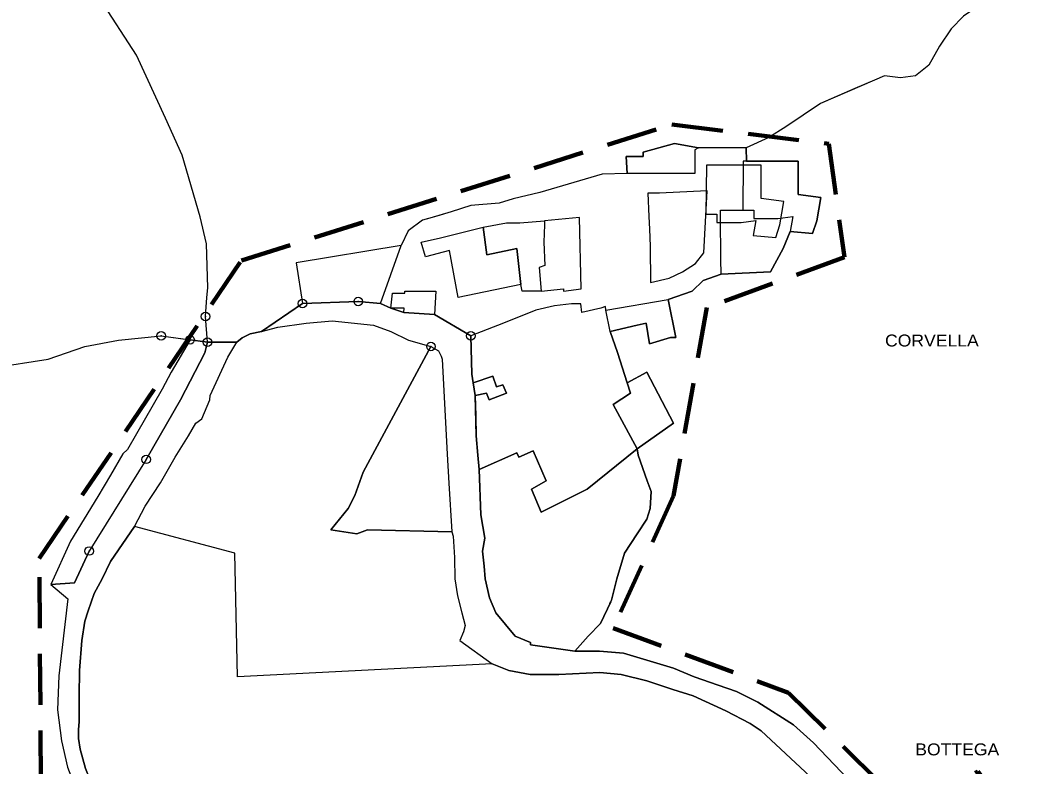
# Model space of a CAD drawing. Extents: x 654952 to 658955, y 890426 to 894481.
# Drawn here: x 657741.8 to 657975.8, y 893049.5 to 893224.6 of the extents above; entities that cross this region are included whole.
import ezdxf

# ---------------------------------------------------------------- set-up
doc = ezdxf.new("R2010")
doc.units = 0
doc.header["$LTSCALE"] = 4
doc.header["$PDMODE"] = 32
doc.header["$PDSIZE"] = 2
doc.linetypes.add('MEDIUM_DASHED', pattern=[4.5, 3, -1.5])
for name, color, linetype, lineweight in [('1', 7, 'Continuous', 25), ('18', 7, 'Continuous', 25), ('19', 7, 'Continuous', 25), ('31', 7, 'Continuous', 25), ('35', 7, 'Continuous', 25), ('5', 7, 'Continuous', 25), ('7', 7, 'MEDIUM_DASHED', 100), ('9', 7, 'Continuous', 25)]:
    doc.layers.add(name, color=color, linetype=linetype, lineweight=lineweight)
doc.layers.add('58', color=7, linetype='Continuous')

msp = doc.modelspace()

# ---------------------------------------------------------------- linework, layer by layer
at = {"layer": '1'}
for p, q in [((657889.5, 893171.44), (657889.63, 893162.94)), ((657798.37, 893151.44), (657808, 893158.03))]:
    msp.add_line(p, q, dxfattribs=at)
for points in [[(657912.02, 893194.55), (657900.89, 893194.55), (657895.27, 893195.55), (657887.89, 893193.55), (657887.9, 893192.54), (657883.89, 893192.55), (657884.14, 893188.55), (657878.25, 893188.39), (657863.64, 893184.05), (657857.39, 893182.55)], [(657906.16, 893164.91), (657917.75, 893165.44), (657920.75, 893170.94), (657922.37, 893174.94), (657927.63, 893174.44), (657928.63, 893177.44), (657929.54, 893182.92), (657924.25, 893183.62), (657924.25, 893191.44), (657912.13, 893191.44), (657912.02, 893194.55)], [(657889.63, 893162.94), (657894, 893163.94), (657897.13, 893165.44), (657900.13, 893167.44), (657902.13, 893169.94), (657902.87, 893184.44), (657891.75, 893183.94), (657889.03, 893183.94), (657889.25, 893178.44), (657889.37, 893175.44), (657889.5, 893171.44)], [(657857.39, 893182.55), (657854.14, 893181.55), (657847.52, 893181.05), (657842.89, 893179.55), (657839.52, 893178.55)], [(657839.52, 893178.55), (657836.14, 893177.55), (657832.77, 893175.05), (657831.16, 893171.66), (657806.52, 893167.55)], [(657806.52, 893167.55), (657808, 893158.03), (657821.09, 893158.47)], [(657858.25, 893122.94), (657858.75, 893121.94), (657862.13, 893123.44), (657865.13, 893116.44), (657861.75, 893114.44), (657863.99, 893109.05), (657874.75, 893114.44), (657886.5, 893123.94), (657880.89, 893134.28), (657884.9, 893136.95), (657881.89, 893146.55), (657880.13, 893151.44), (657886.5, 893152.94), (657888.63, 893153.44), (657889.39, 893148.55), (657894.27, 893150.05), (657895.52, 893150.05), (657893.75, 893158.94), (657899.37, 893160.94), (657902, 893163.44), (657906.16, 893164.91)], [(657821.09, 893158.47), (657826.32, 893157.98), (657828.75, 893156.94), (657831.75, 893155.94), (657839, 893155.44), (657847.5, 893150.44)], [(657881.89, 893146.55), (657880.12, 893151.44), (657879.13, 893156.44), (657879.08, 893157.28), (657878, 893156.94), (657873.5, 893155.94), (657873.25, 893157.94), (657871.13, 893157.94), (657867.13, 893157.44), (657862.75, 893156.44), (657855.13, 893153.44), (657847.5, 893150.44), (657847.75, 893141.44), (657848, 893139.44), (657852.63, 893140.94), (657853.5, 893138.44), (657855, 893138.94), (657855.87, 893136.94), (657851.75, 893135.44), (657851.13, 893136.94), (657848.5, 893136.44), (657848.63, 893131.69), (657848.75, 893126.94), (657849.13, 893122.44), (657849.46, 893119.03), (657858.25, 893122.94)], [(657847.5, 893150.44), (657847.75, 893141.44), (657848, 893139.44), (657848.5, 893136.44), (657848.75, 893126.94), (657849.13, 893122.44), (657849.46, 893119.03), (657858.25, 893122.94)], [(657884.9, 893136.95), (657884.15, 893139.41), (657881.89, 893146.55)], [(657858.25, 893122.94), (657858.75, 893121.94), (657862.13, 893123.44), (657865.13, 893116.44), (657861.75, 893114.44), (657863.99, 893109.05), (657874.75, 893114.44), (657886.5, 893123.94), (657880.89, 893134.28), (657884.9, 893136.95)]]:
    msp.add_lwpolyline(points, dxfattribs=at)
for points in [[(657887.89, 893193.55), (657895.27, 893195.55), (657900.9, 893194.54), (657900.02, 893194.05), (657900.02, 893188.55), (657884.14, 893188.55), (657883.9, 893192.54), (657887.89, 893192.55)], [(657911.37, 893191.44), (657911.25, 893179.94), (657913.87, 893179.94), (657913.87, 893177.94), (657919.5, 893177.94), (657923, 893178.44), (657922.37, 893174.94), (657927.63, 893174.44), (657928.63, 893177.44), (657929.54, 893182.92), (657924.25, 893183.62), (657924.25, 893191.44), (657912.13, 893191.44)], [(657902.71, 893190.49), (657902.59, 893178.99), (657905.21, 893178.99), (657905.21, 893176.99), (657910.84, 893176.99), (657914.34, 893177.49), (657913.71, 893173.99), (657918.97, 893173.49), (657919.97, 893176.49), (657920.88, 893181.97), (657915.59, 893182.67), (657915.59, 893190.49), (657903.47, 893190.49)], [(657911.25, 893179.94), (657913.87, 893179.94), (657913.87, 893177.94), (657919.5, 893177.94), (657923, 893178.44), (657922.37, 893174.94), (657920.75, 893170.94), (657917.75, 893165.44), (657906.16, 893164.91), (657906.13, 893168.44), (657906.02, 893178.44), (657906, 893179.94)], [(657851.25, 893169.44), (657850.37, 893175.94), (657855.87, 893176.94), (657859, 893176.94), (657864.78, 893177.45), (657864.75, 893176.44), (657864.63, 893172.44), (657864.87, 893166.94), (657863.5, 893166.44), (657864, 893160.94), (657859.5, 893160.94), (657859.25, 893162.44), (657858.25, 893170.94)], [(657864.75, 893176.44), (657864.63, 893172.44), (657864.87, 893166.94), (657863.5, 893166.44), (657864, 893160.94), (657869.25, 893161.44), (657869.25, 893160.94), (657873.37, 893161.44), (657872.98, 893178.18), (657864.78, 893177.45)], [(657842.5, 893170.44), (657836.87, 893168.94), (657835.87, 893172.44), (657840.37, 893173.44), (657845.37, 893174.69), (657850.37, 893175.94), (657851.25, 893169.44), (657858.25, 893170.94), (657859.25, 893162.44), (657844.5, 893159.44)], [(657808, 893158.03), (657821.09, 893158.47), (657826.32, 893157.98), (657831.14, 893171.64), (657806.5, 893167.53)], [(657829.13, 893160.44), (657832, 893160.44), (657832, 893160.94), (657839.25, 893160.94), (657839, 893155.44), (657831.75, 893155.94), (657831.87, 893156.94), (657828.75, 893156.94)], [(657879.13, 893156.44), (657893.75, 893158.94), (657895.52, 893150.05), (657894.27, 893150.05), (657889.39, 893148.55), (657888.63, 893153.44), (657886.5, 893152.94), (657880.12, 893151.44)], [(657852.63, 893140.94), (657848, 893139.44), (657848.5, 893136.44), (657851.13, 893136.94), (657851.75, 893135.44), (657855.87, 893136.94), (657855, 893138.94), (657853.5, 893138.44)]]:
    msp.add_lwpolyline(points, close=True, dxfattribs=at)
for p in [(657808, 893158.03), (657821.09, 893158.47), (657847.5, 893150.44)]:
    msp.add_point(p, dxfattribs=at)
at = {"layer": '18'}
for p, q in [((657781.65, 893149.49), (657777.25, 893141.94)), ((657777.25, 893141.94), (657775.13, 893137.94))]:
    msp.add_line(p, q, dxfattribs=at)
for points in [[(657771.37, 893121.44), (657779.37, 893135.44), (657785.13, 893146.44), (657785.75, 893148.94), (657781.65, 893149.49)], [(657843, 893104.44), (657823.25, 893104.94), (657820.75, 893103.94), (657814.63, 893104.94), (657818.75, 893109.94), (657820.25, 893112.94), (657822.25, 893118.44), (657838.13, 893147.94), (657839.88, 893146.94), (657840.19, 893146.31), (657840.5, 893145.69), (657840.75, 893144.94)], [(657840.75, 893144.94), (657841.94, 893122.69), (657842.34, 893115.86), (657843, 893104.44)], [(657775.13, 893137.94), (657767.01, 893123.73), (657765.88, 893122.73), (657763.01, 893117.73), (657760.01, 893112.73), (657753.63, 893102.23), (657749.02, 893092.12), (657754.58, 893092.44), (657758, 893099.94)]]:
    msp.add_lwpolyline(points, dxfattribs=at)
for p in [(657781.65, 893149.49), (657771.37, 893121.44), (657758, 893099.94)]:
    msp.add_point(p, dxfattribs=at)
at = {"layer": '19'}
for points in [[(657768.62, 893105.66), (657763, 893097.44), (657761, 893093.44), (657759.13, 893089.94), (657757.75, 893085.94), (657757, 893083.44), (657756.25, 893078.94), (657755.75, 893071.94), (657755.63, 893065.94), (657755.63, 893059.94), (657755.5, 893057.94), (657755.5, 893055.94), (657755.88, 893053.44), (657756.5, 893051.19), (657757.13, 893048.94), (657758.13, 893046.44), (657759.48, 893042.94), (657927.42, 893042.94), (657927.02, 893047.01), (657915.59, 893057.77)], [(657915.59, 893057.77), (657913, 893059.44), (657907.25, 893062.44), (657899.63, 893065.94), (657894.87, 893067.44), (657888.75, 893069.44), (657882.75, 893070.94), (657877.75, 893071.44), (657868.13, 893070.94), (657861.37, 893070.94), (657856.37, 893071.94), (657852.5, 893073.44), (657792.75, 893070.44), (657792.13, 893099.44), (657768.62, 893105.66)]]:
    msp.add_lwpolyline(points, dxfattribs=at)
at = {"layer": '31'}
for points in [[(657993.63, 893244.44), (657991.13, 893240.44), (657986.37, 893235.94), (657980.75, 893232.44), (657975.13, 893230.44), (657969.25, 893228.44), (657966, 893227.44), (657963, 893225.44), (657960.13, 893222.44), (657957.38, 893218.44), (657954.87, 893213.94), (657951.75, 893211.44), (657948.25, 893210.94), (657945.7, 893211.28)], [(657945.7, 893211.28), (657944.5, 893211.44), (657942.13, 893210.44), (657937.5, 893208.44), (657929.5, 893204.94), (657921.37, 893199.44), (657917.37, 893196.94), (657912.02, 893194.55), (657912.13, 893191.44), (657924.25, 893191.44), (657924.25, 893183.62), (657929.54, 893182.92), (657928.63, 893177.44), (657927.63, 893174.44), (657922.37, 893174.94), (657920.75, 893170.94), (657917.75, 893165.44), (657906.16, 893164.91), (657902, 893163.44), (657899.37, 893160.94), (657893.75, 893158.94), (657895.52, 893150.05), (657894.27, 893150.05), (657889.39, 893148.55), (657888.63, 893153.44), (657886.5, 893152.94), (657880.13, 893151.44)], [(657880.13, 893151.44), (657881.89, 893146.55), (657884.15, 893139.41), (657888.75, 893141.94), (657895, 893129.94), (657886.5, 893123.94), (657886.75, 893122.44), (657888.87, 893116.44)], [(657665.82, 893118.07), (657670.25, 893120.44), (657680.87, 893126.44), (657687.75, 893128.94), (657694.75, 893130.94), (657702.5, 893134.44), (657710.63, 893136.94), (657723.13, 893140.44), (657735.25, 893142.94), (657748.37, 893144.94), (657757, 893147.94), (657764.87, 893149.44), (657774.87, 893150.44), (657781.65, 893149.49), (657777.25, 893141.94), (657775.13, 893137.94)], [(657775.13, 893137.94), (657767.01, 893123.73), (657765.88, 893122.73), (657763.01, 893117.73), (657760.01, 893112.73), (657753.63, 893102.23), (657749.02, 893092.12)], [(657888.87, 893116.44), (657889.75, 893113.94), (657889.5, 893109.94), (657888.75, 893107.44), (657886.5, 893103.94), (657883.5, 893099.44), (657881.75, 893093.44), (657880.5, 893088.44), (657880.1, 893087.6), (657880.3, 893088.02), (657877.87, 893082.94), (657875, 893079.94), (657871.87, 893076.44), (657877.63, 893076.44), (657883.25, 893075.94), (657895, 893072.44), (657899.87, 893070.44), (657905.5, 893068.44), (657909.75, 893066.94), (657914.75, 893064.44), (657923.17, 893059.18), (657927.87, 893054.94), (657935.94, 893046.44)], [(657749.02, 893092.12), (657753.01, 893088.7), (657750.86, 893070.62), (657750.6, 893062.66), (657751.53, 893055.36), (657752.89, 893049.18), (657758.65, 893034.52), (657762.55, 893024.6), (657763.91, 893018.16), (657764.24, 893010.53), (657763.29, 893003.28), (657761.19, 892995.37), (657758, 892987.59), (657738.18, 893003.15)]]:
    msp.add_lwpolyline(points, dxfattribs=at)
at = {"layer": '35'}
for p, q in [((657808, 893158.03), (657798.37, 893151.44)), ((657774.87, 893150.44), (657785.75, 893148.94))]:
    msp.add_line(p, q, dxfattribs=at)
for points in [[(657785.75, 893148.94), (657785.25, 893154.99), (657785.55, 893159.43), (657785.79, 893161.68), (657785.49, 893172.03), (657783.98, 893178.37), (657779.79, 893192.83), (657775.91, 893201.54), (657769.07, 893216.31), (657760.53, 893229.52)], [(657785.25, 893154.99), (657785.55, 893159.43), (657785.79, 893161.68), (657785.49, 893172.03), (657783.98, 893178.37), (657779.79, 893192.83), (657775.91, 893201.54), (657769.07, 893216.31), (657760.53, 893229.52)], [(657963, 893225.44), (657960.13, 893222.44), (657957.38, 893218.44), (657954.87, 893213.94), (657951.75, 893211.44), (657948.25, 893210.94), (657945.7, 893211.28), (657944.5, 893211.44), (657942.13, 893210.44), (657929.5, 893204.94), (657921.37, 893199.44), (657917.37, 893196.94), (657912.02, 893194.55), (657900.9, 893194.54), (657895.28, 893195.54), (657887.89, 893193.55), (657887.9, 893192.54), (657883.9, 893192.54), (657884.14, 893188.55), (657878.25, 893188.39), (657863.64, 893184.05), (657857.39, 893182.55), (657854.14, 893181.54), (657847.52, 893181.04), (657842.89, 893179.55), (657837.84, 893178.04), (657836.14, 893177.54), (657832.78, 893175.04), (657831.16, 893171.66), (657806.52, 893167.54), (657808, 893158.03)], [(657798.37, 893151.44), (657795.75, 893150.94), (657793.87, 893149.94), (657792.63, 893148.94), (657785.75, 893148.94), (657785.25, 893154.99)], [(657676.59, 893105.59), (657670.27, 893111.6), (657665.82, 893118.07), (657680.87, 893126.44), (657687.75, 893128.94), (657694.75, 893130.94), (657702.5, 893134.44), (657723.13, 893140.44), (657735.25, 893142.94), (657748.37, 893144.94), (657757, 893147.94), (657764.87, 893149.44), (657774.87, 893150.44)]]:
    msp.add_lwpolyline(points, dxfattribs=at)
for p in [(657785.25, 893154.99), (657774.87, 893150.44), (657785.75, 893148.94)]:
    msp.add_point(p, dxfattribs=at)
at = {"layer": '5'}
for points in [[(657850.59, 893096.42), (657850.25, 893099.94), (657850.75, 893102.94), (657849.87, 893108.44), (657849.46, 893119.03), (657849.13, 893122.44), (657848.75, 893126.94), (657848.5, 893136.44), (657848, 893139.44), (657847.75, 893141.44), (657847.5, 893150.44), (657839, 893155.44), (657831.75, 893155.94), (657828.75, 893156.94), (657826.32, 893157.98), (657821.09, 893158.47), (657808, 893158.03), (657798.37, 893151.44)], [(657808.84, 893153.4), (657815, 893153.94), (657824.63, 893152.94), (657828.75, 893151.44), (657832.88, 893149.44), (657838.13, 893147.94), (657839.88, 893146.94), (657840.19, 893146.31), (657840.5, 893145.69), (657840.75, 893144.94)], [(657798.37, 893151.44), (657802.25, 893152.44), (657808.84, 893153.4)], [(657840.75, 893144.94), (657841.94, 893122.69), (657842.34, 893115.86), (657843, 893104.44)], [(657843, 893104.44), (657843.37, 893103.44), (657843.63, 893098.44), (657843.75, 893093.44), (657844.37, 893089.44), (657845.37, 893085.44), (657846.13, 893082.44), (657845.75, 893080.94), (657844.87, 893078.94), (657852.5, 893073.44), (657856.37, 893071.94)], [(657935.94, 893046.44), (657927.87, 893054.94), (657923.17, 893059.18), (657914.75, 893064.44), (657909.75, 893066.94), (657905.5, 893068.44), (657899.87, 893070.44), (657895, 893072.44), (657883.25, 893075.94), (657877.63, 893076.44), (657871.87, 893076.44), (657861.5, 893077.94), (657861.5, 893078.44), (657857.87, 893079.94), (657853.37, 893085.44), (657851.87, 893088.94), (657850.87, 893093.44), (657850.59, 893096.42)], [(657856.37, 893071.94), (657861.37, 893070.94), (657868.13, 893070.94), (657877.75, 893071.44), (657882.75, 893070.94), (657888.75, 893069.44), (657894.87, 893067.44), (657899.63, 893065.94), (657907.25, 893062.44), (657913, 893059.44), (657915.59, 893057.77), (657927.02, 893047.01)]]:
    msp.add_lwpolyline(points, dxfattribs=at)
at = {"layer": '7'}
msp.add_lwpolyline([(657691.52, 892856.93), (657700.1, 892905.18), (657716.04, 892939.12), (657738.11, 892964.47), (657720.54, 892980.83), (657736.88, 893006.17), (657758.54, 892994.31), (657762.63, 893015.17), (657746.69, 893045.84), (657746.28, 893098.18), (657793.69, 893168.1), (657894.63, 893200), (657931.41, 893195.5), (657935.09, 893168.92), (657902.81, 893157.06), (657895.04, 893112.9), (657880.84, 893081.86), (657922.01, 893066.69), (657950.13, 893038.88), (657966.34, 893048.2), (657980.93, 893028.74)], dxfattribs=at)
at = {"layer": '9'}
for p, q in [((657785.75, 893148.94), (657792.63, 893148.94)), ((657771.37, 893121.44), (657758, 893099.94))]:
    msp.add_line(p, q, dxfattribs=at)
for points in [[(657808.84, 893153.4), (657815, 893153.94), (657824.63, 893152.94), (657828.75, 893151.44), (657832.88, 893149.44), (657838.13, 893147.94)], [(657786.25, 893135.44), (657786.37, 893136.44), (657790.5, 893145.44), (657792.63, 893148.94), (657793.87, 893149.94), (657795.75, 893150.94), (657798.37, 893151.44), (657802.25, 893152.44), (657808.84, 893153.4)], [(657786.25, 893135.44), (657786.37, 893136.44), (657790.5, 893145.44), (657792.63, 893148.94), (657785.75, 893148.94), (657785.13, 893146.44), (657779.37, 893135.44), (657771.37, 893121.44)], [(657838.13, 893147.94), (657822.25, 893118.44), (657820.25, 893112.94), (657818.75, 893109.94), (657814.63, 893104.94), (657820.75, 893103.94), (657823.25, 893104.94), (657843, 893104.44)], [(657771.13, 893110.44), (657774.75, 893115.94), (657778.13, 893121.94), (657781.25, 893126.94), (657783, 893129.94), (657784.37, 893130.94), (657786.25, 893135.44)], [(657771.13, 893110.44), (657774.75, 893115.94), (657778.13, 893121.94), (657781.25, 893126.94), (657783, 893129.94), (657784.37, 893130.94), (657786.25, 893135.44)], [(657863.99, 893109.05), (657861.75, 893114.44), (657865.13, 893116.44), (657862.13, 893123.44), (657858.75, 893121.94), (657858.25, 893122.94)], [(657880.1, 893087.6), (657880.5, 893088.44), (657881.75, 893093.44), (657883.5, 893099.44), (657886.5, 893103.94), (657888.75, 893107.44), (657889.5, 893109.94), (657889.75, 893113.94), (657888.87, 893116.44), (657886.75, 893122.44), (657886.5, 893123.94), (657874.75, 893114.44), (657863.99, 893109.05)], [(657858.25, 893122.94), (657849.46, 893119.03), (657849.87, 893108.44), (657850.75, 893102.94)], [(657755.63, 893059.94), (657755.63, 893065.94), (657755.75, 893071.94), (657756.25, 893078.94), (657757, 893083.44), (657757.75, 893085.94), (657759.13, 893089.94), (657761, 893093.44), (657763, 893097.44), (657768.62, 893105.66), (657771.13, 893110.44)], [(657852.5, 893073.44), (657792.75, 893070.44), (657792.13, 893099.44), (657768.62, 893105.66), (657771.13, 893110.44)], [(657843, 893104.44), (657843.37, 893103.44), (657843.63, 893098.44), (657843.75, 893093.44), (657844.37, 893089.44), (657845.37, 893085.44), (657846.13, 893082.44), (657845.75, 893080.94), (657844.87, 893078.94), (657852.5, 893073.44)], [(657850.75, 893102.94), (657850.25, 893099.94), (657850.59, 893096.42), (657850.87, 893093.44), (657851.87, 893088.94), (657853.37, 893085.44), (657857.87, 893079.94), (657861.5, 893078.44), (657861.5, 893077.94), (657871.87, 893076.44), (657875, 893079.94), (657877.87, 893082.94), (657880.3, 893088.02), (657880.1, 893087.6)], [(657758, 893099.94), (657754.58, 893092.44), (657749.02, 893092.12)], [(657749.02, 893092.12), (657753.01, 893088.7), (657750.86, 893070.62), (657750.6, 893062.66), (657751.53, 893055.36), (657752.89, 893049.18), (657758.65, 893034.52), (657762.55, 893024.6), (657763.91, 893018.16), (657764.24, 893010.53), (657763.29, 893003.28), (657761.19, 892995.37), (657758, 892987.59)], [(657769.37, 893011.44), (657768.87, 893012.94), (657768.75, 893016.94), (657767.25, 893024.94), (657765.63, 893029.44), (657763.5, 893033.94), (657760.37, 893040.44), (657759.48, 893042.94), (657758.13, 893046.44), (657757.13, 893048.94), (657756.5, 893051.19), (657755.88, 893053.44), (657755.5, 893055.94), (657755.5, 893057.94), (657755.63, 893059.94)]]:
    msp.add_lwpolyline(points, dxfattribs=at)
msp.add_lwpolyline([(657880.9, 893134.29), (657886.5, 893123.94), (657895, 893129.94), (657888.75, 893141.94), (657884.15, 893139.41), (657884.9, 893136.96)], close=True, dxfattribs=at)
for p in [(657838.13, 893147.94), (657771.37, 893121.44), (657758, 893099.94)]:
    msp.add_point(p, dxfattribs=at)

# ---------------------------------------------------------------- texts
at = {"layer": '58', "width": 1.1}
for s, p in [('CORVELLA', (657944.61, 893147.93)), ('BOTTEGA', (657951.7, 893051.99))]:
    msp.add_text(s, height=2.801, dxfattribs=at).set_placement(p)

doc.saveas('drawing.dxf')
